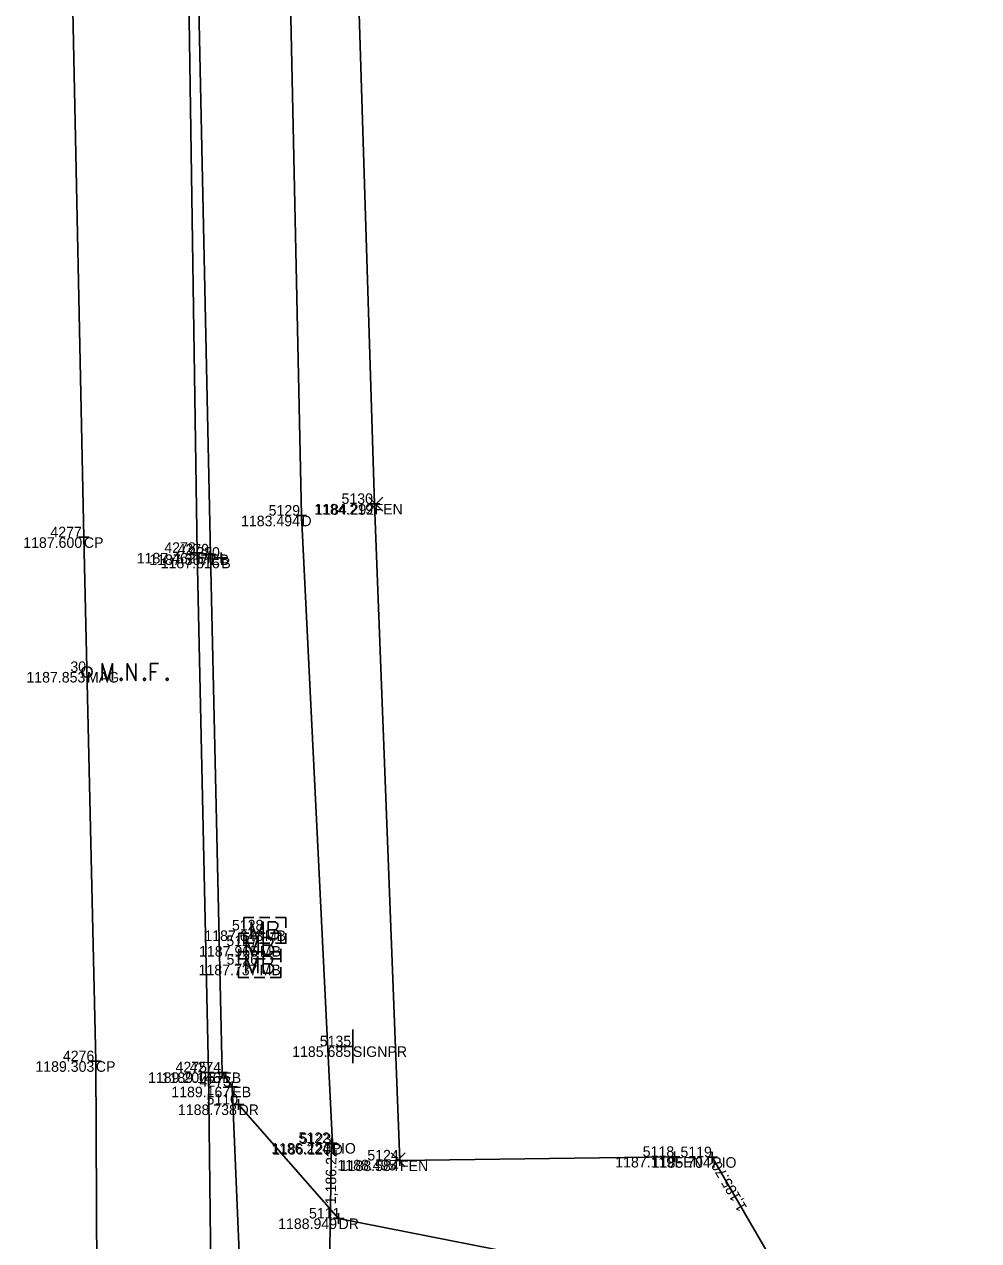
# Model space of a CAD drawing. Extents: x 2044996 to 2050343, y 455232 to 458054.
# Drawn here: x 2047607.5 to 2047697.8, y 457864.6 to 457979.7 of the extents above; entities that cross this region are included whole.
import ezdxf

# ---------------------------------------------------------------- set-up
doc = ezdxf.new("R2010")
doc.units = 0
for name, color, linetype in [('DR_X_Ditch', 7, 'Continuous'), ('DR_X_Elev_Flow', 7, 'Continuous'), ('DR_X_Storm_Sewer', 7, 'Continuous'), ('DT_X_Contour_Major', 7, 'Continuous'), ('DT_X_Contour_Minor', 7, 'Continuous'), ('DT_X_Contour_Text', 7, 'Continuous'), ('DT_X_Spot_Elev', 7, 'Continuous'), ('DT_X_Triangles', 7, 'Continuous'), ('DT_X_Void', 7, 'Continuous'), ('PV_X_COP', 7, 'Continuous'), ('PV_X_Driveway', 7, 'Continuous'), ('PV_X_EOP', 7, 'Continuous'), ('PV_X_Shoulder_Aggregate', 7, 'Continuous'), ('RD_X_Cells', 7, 'Continuous'), ('RD_X_Fence', 7, 'Continuous'), ('SC_Scratch1', 7, 'Continuous'), ('SN_X_Public', 7, 'Continuous')]:
    doc.layers.add(name, color=color, linetype=linetype)

msp = doc.modelspace()

# ---------------------------------------------------------------- linework, layer by layer
at = {"layer": 'DR_X_Ditch'}
msp.add_lwpolyline([(2047636.7, 457873.73), (2047633.74, 457933.19), (2047632.12, 458009.84)], dxfattribs=at)
at = {"layer": 'DR_X_Elev_Flow'}
for p, q in [((2047636.59, 457874.32), (2047636.59, 457873.32)), ((2047636.09, 457873.82), (2047637.09, 457873.82)), ((2047636.59, 457873.82), (2047636.59, 457873.82)), ((2047672.61, 457872.98), (2047672.61, 457871.98)), ((2047672.11, 457872.48), (2047673.11, 457872.48)), ((2047672.61, 457872.48), (2047672.61, 457872.48))]:
    msp.add_line(p, q, dxfattribs=at)
at = {"layer": 'DR_X_Storm_Sewer'}
for p, q in [((2047635.9, 457828.32), (2047636.59, 457873.82)), ((2047697.83, 457829.07), (2047672.61, 457872.48))]:
    msp.add_line(p, q, dxfattribs=at)
at = {"layer": 'DT_X_Contour_Major'}
for points in [[(2047614.89, 457917.59), (2047614.89, 457919.19), (2047615.39, 457917.59), (2047615.88, 457919.19), (2047615.88, 457917.59)], [(2047617.26, 457917.59), (2047617.26, 457919.19), (2047618.08, 457917.59), (2047618.08, 457919.19)], [(2047620.23, 457919.19), (2047619.47, 457919.19), (2047619.47, 457917.59)], [(2047616.65, 457917.8), (2047616.71, 457917.8), (2047616.74, 457917.78), (2047616.77, 457917.73), (2047616.77, 457917.67), (2047616.74, 457917.61), (2047616.71, 457917.59), (2047616.65, 457917.59), (2047616.62, 457917.61), (2047616.58, 457917.67), (2047616.58, 457917.73), (2047616.62, 457917.78), (2047616.65, 457917.8)], [(2047618.87, 457917.8), (2047618.92, 457917.8), (2047618.95, 457917.78), (2047618.99, 457917.73), (2047618.99, 457917.67), (2047618.95, 457917.61), (2047618.92, 457917.59), (2047618.87, 457917.59), (2047618.83, 457917.61), (2047618.8, 457917.67), (2047618.8, 457917.73), (2047618.83, 457917.78), (2047618.87, 457917.8)], [(2047619.47, 457918.41), (2047620.01, 457918.41)], [(2047621.02, 457917.8), (2047621.07, 457917.8), (2047621.1, 457917.78), (2047621.14, 457917.73), (2047621.14, 457917.67), (2047621.1, 457917.61), (2047621.07, 457917.59), (2047621.02, 457917.59), (2047620.98, 457917.61), (2047620.95, 457917.67), (2047620.95, 457917.73), (2047620.98, 457917.78), (2047621.02, 457917.8)]]:
    msp.add_lwpolyline(points, dxfattribs=at)
msp.add_circle((2047613.45, 457918.4), 0.497, dxfattribs=at)
at = {"layer": 'DT_X_Spot_Elev'}
for p, q in [((2047640.11, 457933.6), (2047641.44, 457934.93)), ((2047640.11, 457934.93), (2047641.44, 457933.6)), ((2047642.23, 457871.56), (2047643.56, 457872.89)), ((2047642.23, 457872.89), (2047643.56, 457871.56))]:
    msp.add_line(p, q, dxfattribs=at)
at = {"layer": 'DT_X_Void'}
for p, q in [((2047640.16, 457934.3), (2047641.16, 457934.3)), ((2047640.66, 457934.8), (2047640.66, 457933.8)), ((2047640.66, 457934.3), (2047640.66, 457934.3)), ((2047633.24, 457933.19), (2047634.24, 457933.19)), ((2047633.74, 457933.69), (2047633.74, 457932.69)), ((2047633.74, 457933.19), (2047633.74, 457933.19)), ((2047613.16, 457931.64), (2047613.16, 457930.64)), ((2047612.66, 457931.14), (2047613.66, 457931.14)), ((2047613.16, 457931.14), (2047613.16, 457931.14)), ((2047623.39, 457929.67), (2047624.39, 457929.67)), ((2047623.89, 457930.17), (2047623.89, 457929.17)), ((2047623.89, 457929.67), (2047623.89, 457929.67)), ((2047624.63, 457929.52), (2047625.63, 457929.52)), ((2047625.13, 457930.02), (2047625.13, 457929.02)), ((2047625.13, 457929.52), (2047625.13, 457929.52)), ((2047625.66, 457929.21), (2047626.66, 457929.21)), ((2047626.16, 457929.71), (2047626.16, 457928.71)), ((2047626.16, 457929.21), (2047626.16, 457929.21)), ((2047614.29, 457882.06), (2047614.29, 457881.06)), ((2047613.79, 457881.56), (2047614.79, 457881.56)), ((2047614.29, 457881.56), (2047614.29, 457881.56)), ((2047624.96, 457881.01), (2047624.96, 457880.01)), ((2047626.26, 457881), (2047626.26, 457880)), ((2047624.46, 457880.51), (2047625.46, 457880.51)), ((2047624.96, 457880.51), (2047624.96, 457880.51)), ((2047625.76, 457880.5), (2047626.76, 457880.5)), ((2047626.26, 457880.5), (2047626.26, 457880.5)), ((2047627.2, 457879.65), (2047627.2, 457878.65)), ((2047626.7, 457879.15), (2047627.7, 457879.15)), ((2047627.2, 457879.15), (2047627.2, 457879.15)), ((2047627.29, 457877.47), (2047628.29, 457877.47)), ((2047627.79, 457877.97), (2047627.79, 457876.97)), ((2047627.79, 457877.47), (2047627.79, 457877.47)), ((2047636.7, 457874.23), (2047636.7, 457873.23)), ((2047636.2, 457873.73), (2047637.2, 457873.73)), ((2047636.7, 457873.73), (2047636.7, 457873.73)), ((2047669.05, 457873.01), (2047669.05, 457872.01)), ((2047642.57, 457872.17), (2047643.57, 457872.17)), ((2047643.07, 457872.67), (2047643.07, 457871.67)), ((2047643.07, 457872.17), (2047643.07, 457872.17)), ((2047668.55, 457872.51), (2047669.55, 457872.51)), ((2047669.05, 457872.51), (2047669.05, 457872.51)), ((2047637.26, 457867.18), (2047637.26, 457866.18)), ((2047636.76, 457866.68), (2047637.76, 457866.68)), ((2047637.26, 457866.68), (2047637.26, 457866.68))]:
    msp.add_line(p, q, dxfattribs=at)
at = {"layer": 'PV_X_COP'}
msp.add_lwpolyline([(2047630.7, 457032.77), (2047629.57, 457079.46), (2047628.83, 457121.31), (2047627.83, 457168.37), (2047627.23, 457213.89), (2047626.35, 457261.41), (2047625.27, 457313.88), (2047624.14, 457367.69), (2047623.14, 457414.96), (2047622.16, 457463.48), (2047621.21, 457510.6), (2047620.34, 457561.9), (2047619.47, 457614.83), (2047618.33, 457662.23), (2047617.51, 457713.13), (2047616.39, 457759.38), (2047615.44, 457807.27), (2047614.41, 457854.52), (2047614.29, 457881.56), (2047613.16, 457931.14), (2047612.06, 457984.05), (2047611.48, 458032.26), (2047610.91, 458052.26)], dxfattribs=at)
at = {"layer": 'PV_X_Driveway'}
msp.add_lwpolyline([(2047627.79, 457877.47), (2047637.26, 457866.68), (2047656.32, 457862.93), (2047675.59, 457863.11)], dxfattribs=at)
at = {"layer": 'PV_X_EOP'}
for p, q in [((2047623.89, 457929.67), (2047623.05, 457984.3)), ((2047624.96, 457880.51), (2047623.89, 457929.67)), ((2047625.26, 457852.62), (2047624.96, 457880.51))]:
    msp.add_line(p, q, dxfattribs=at)
at = {"layer": 'PV_X_Shoulder_Aggregate'}
msp.add_lwpolyline([(2047636.93, 457312.89), (2047635.93, 457367.47), (2047634.97, 457414.6), (2047633.92, 457462.12), (2047633.13, 457509.72), (2047632.17, 457560.26), (2047631.16, 457614.81), (2047630.46, 457661.29), (2047629.4, 457713.73), (2047628.5, 457758.09), (2047627.36, 457807.43), (2047627.48, 457822.09), (2047628.61, 457825.87), (2047628.68, 457844.07), (2047627.2, 457879.15), (2047626.26, 457880.5), (2047625.13, 457929.52), (2047623.96, 457984.29), (2047622.9, 458032.45), (2047622.9, 458052.72)], dxfattribs=at)
at = {"layer": 'RD_X_Cells'}
for p, q in [((2047629.77, 457895.16), (2047630.77, 457895.16)), ((2047629.29, 457893.68), (2047630.3, 457893.68)), ((2047630.28, 457893.94), (2047630.28, 457893.94)), ((2047629.77, 457892.72), (2047630.77, 457892.72)), ((2047629.81, 457892.46), (2047629.81, 457892.46)), ((2047629.28, 457891.92), (2047630.28, 457891.92)), ((2047629.29, 457891.24), (2047630.3, 457891.24)), ((2047629.79, 457890.7), (2047629.79, 457890.7)), ((2047629.28, 457889.48), (2047630.28, 457889.48))]:
    msp.add_line(p, q, dxfattribs=at)
for points in [[(2047628.28, 457894.19), (2047628.28, 457895.16), (2047629.25, 457895.16)], [(2047628.99, 457893.14), (2047628.99, 457894.74), (2047629.57, 457893.14), (2047630.12, 457894.74), (2047630.12, 457893.14)], [(2047631.31, 457894.01), (2047631.37, 457894.07), (2047631.41, 457894.11), (2047631.43, 457894.15), (2047631.44, 457894.17), (2047631.47, 457894.22), (2047631.48, 457894.26), (2047631.51, 457894.35), (2047631.51, 457894.39), (2047631.51, 457894.44), (2047631.5, 457894.51), (2047631.47, 457894.58), (2047631.43, 457894.63), (2047631.37, 457894.68), (2047631.32, 457894.7), (2047631.29, 457894.72), (2047631.23, 457894.74), (2047630.61, 457894.74), (2047630.61, 457893.14), (2047631.31, 457893.14), (2047631.39, 457893.19), (2047631.47, 457893.25), (2047631.53, 457893.35), (2047631.57, 457893.47), (2047631.58, 457893.58), (2047631.58, 457893.66), (2047631.56, 457893.73), (2047631.51, 457893.85), (2047631.44, 457893.92), (2047631.31, 457894.01), (2047630.61, 457894.01)], [(2047631.29, 457895.16), (2047632.28, 457895.16), (2047632.28, 457894.19)], [(2047627.81, 457892.71), (2047627.81, 457893.68), (2047628.78, 457893.68)], [(2047629.25, 457892.72), (2047628.28, 457892.72), (2047628.28, 457893.69)], [(2047630.81, 457893.68), (2047631.81, 457893.68), (2047631.81, 457892.71)], [(2047632.28, 457893.69), (2047632.28, 457892.72), (2047631.29, 457892.72)], [(2047628.51, 457891.66), (2047628.51, 457893.26), (2047629.09, 457891.66), (2047629.64, 457893.26), (2047629.64, 457891.66)], [(2047630.83, 457892.53), (2047630.89, 457892.59), (2047630.93, 457892.63), (2047630.95, 457892.67), (2047630.97, 457892.69), (2047630.99, 457892.74), (2047631, 457892.78), (2047631.03, 457892.87), (2047631.03, 457892.91), (2047631.03, 457892.96), (2047631.02, 457893.03), (2047630.99, 457893.1), (2047630.95, 457893.15), (2047630.89, 457893.2), (2047630.84, 457893.22), (2047630.82, 457893.24), (2047630.75, 457893.26), (2047630.14, 457893.26), (2047630.14, 457891.66), (2047630.83, 457891.66), (2047630.92, 457891.71), (2047630.99, 457891.77), (2047631.05, 457891.87), (2047631.09, 457891.99), (2047631.11, 457892.1), (2047631.11, 457892.18), (2047631.08, 457892.25), (2047631.03, 457892.37), (2047630.97, 457892.44), (2047630.83, 457892.53), (2047630.14, 457892.53)], [(2047627.79, 457890.95), (2047627.79, 457891.92), (2047628.76, 457891.92)], [(2047628.78, 457891.24), (2047627.81, 457891.24), (2047627.81, 457892.21)], [(2047628.49, 457889.9), (2047628.49, 457891.5), (2047629.07, 457889.9), (2047629.62, 457891.5), (2047629.62, 457889.9)], [(2047630.81, 457890.77), (2047630.87, 457890.83), (2047630.91, 457890.87), (2047630.94, 457890.91), (2047630.95, 457890.93), (2047630.97, 457890.98), (2047630.99, 457891.02), (2047631.01, 457891.11), (2047631.01, 457891.15), (2047631.01, 457891.2), (2047631, 457891.27), (2047630.97, 457891.34), (2047630.94, 457891.39), (2047630.87, 457891.44), (2047630.82, 457891.46), (2047630.8, 457891.47), (2047630.73, 457891.5), (2047630.12, 457891.5), (2047630.12, 457889.9), (2047630.81, 457889.9), (2047630.9, 457889.95), (2047630.97, 457890.01), (2047631.04, 457890.11), (2047631.07, 457890.23), (2047631.09, 457890.34), (2047631.09, 457890.42), (2047631.06, 457890.49), (2047631.01, 457890.6), (2047630.95, 457890.68), (2047630.81, 457890.77), (2047630.12, 457890.77)], [(2047630.79, 457891.92), (2047631.79, 457891.92), (2047631.79, 457890.95)], [(2047631.81, 457892.21), (2047631.81, 457891.24), (2047630.81, 457891.24)], [(2047628.76, 457889.48), (2047627.79, 457889.48), (2047627.79, 457890.45)], [(2047631.79, 457890.45), (2047631.79, 457889.48), (2047630.79, 457889.48)]]:
    msp.add_lwpolyline(points, dxfattribs=at)
at = {"layer": 'RD_X_Fence'}
msp.add_lwpolyline([(2047669.05, 457872.51), (2047643.07, 457872.17), (2047640.66, 457934.3), (2047638.33, 458008.93)], dxfattribs=at)
at = {"layer": 'SN_X_Public'}
for p, q in [((2047638.61, 457884.57), (2047638.61, 457881.37)), ((2047638.61, 457882.97), (2047637.01, 457882.97))]:
    msp.add_line(p, q, dxfattribs=at)

# ---------------------------------------------------------------- texts
at = {"layer": 'DT_X_Contour_Minor'}
for s, p in [('1184.219', (2047634.95, 457933.3)), ('1184.292', (2047635.05, 457933.27)), ('1183.494', (2047628.03, 457932.19)), ('1187.600', (2047607.42, 457930.14)), ('1187.462', (2047618.16, 457928.67)), ('1187.367', (2047619.35, 457928.52)), ('1187.316', (2047620.43, 457928.21)), ('1187.853', (2047607.72, 457917.4)), ('1187.643', (2047624.56, 457892.94)), ('1187.965', (2047624.06, 457891.46)), ('1187.737', (2047624.01, 457889.7)), ('1185.685', (2047632.87, 457881.97)), ('1189.303', (2047608.57, 457880.56)), ('1189.200', (2047619.23, 457879.51)), ('1189.146', (2047620.52, 457879.5)), ('1189.167', (2047621.43, 457878.15)), ('1188.738', (2047622.06, 457876.47)), ('1186.224', (2047630.88, 457872.82)), ('1186.120', (2047630.97, 457872.73)), ('1188.495', (2047637.15, 457871.23)), ('1188.584', (2047637.37, 457871.17)), ('1187.119', (2047663.44, 457871.51)), ('1185.704', (2047666.9, 457871.48)), ('1188.949', (2047631.54, 457865.68))]:
    msp.add_text(s, height=1, dxfattribs=at).set_placement(p)
at = {"layer": 'DT_X_Contour_Text'}
for s, p in [('FEN', (2047640.66, 457933.3)), ('D', (2047633.74, 457932.19)), ('CP', (2047613.16, 457930.14)), ('EP', (2047623.89, 457928.67)), ('EB', (2047625.13, 457928.52)), ('B', (2047626.16, 457928.21)), ('MAG', (2047613.45, 457917.4)), ('MB', (2047630.28, 457892.94)), ('MB', (2047629.81, 457891.46)), ('MB', (2047629.79, 457889.7)), ('SIGNPR', (2047638.61, 457881.97)), ('CP', (2047614.29, 457880.56)), ('EP', (2047624.96, 457879.51)), ('EB', (2047626.26, 457879.5)), ('EB', (2047627.2, 457878.15)), ('DR', (2047627.79, 457876.47)), ('PIO', (2047636.59, 457872.82)), ('D', (2047636.7, 457872.73)), ('FEN', (2047643.07, 457871.17)), ('FEN', (2047669.05, 457871.51)), ('PIO', (2047672.61, 457871.48)), ('DR', (2047637.26, 457865.68))]:
    msp.add_text(s, height=1, dxfattribs=at).set_placement(p)
at = {"layer": 'DT_X_Triangles'}
for s, p in [('5130', (2047637.54, 457934.3)), ('5129', (2047630.64, 457933.19)), ('4277', (2047609.99, 457931.14)), ('4278', (2047620.77, 457929.67)), ('4279', (2047622.03, 457929.52)), ('4280', (2047623.05, 457929.21)), ('30', (2047611.88, 457918.4)), ('5128', (2047627.17, 457893.94)), ('5127', (2047626.64, 457892.46)), ('5126', (2047626.66, 457890.7)), ('5135', (2047635.48, 457882.97)), ('4276', (2047611.17, 457881.56)), ('4275', (2047621.83, 457880.51)), ('4274', (2047623.17, 457880.5)), ('4273', (2047624.1, 457879.15)), ('5110', (2047624.77, 457877.47)), ('5122', (2047633.47, 457873.82)), ('5123', (2047633.59, 457873.73)), ('5124', (2047639.98, 457872.17)), ('5118', (2047666.04, 457872.51)), ('5119', (2047669.61, 457872.48)), ('5111', (2047634.46, 457866.68))]:
    msp.add_text(s, height=1, dxfattribs=at).set_placement(p)
at = {"layer": 'SC_Scratch1'}
for s, rotation, p in [("1,186.22'", 89.1413, (2047637, 457868.02)), ("1,185.70'", 120.1644, (2047675.95, 457867.71))]:
    msp.add_text(s, height=1, rotation=rotation, dxfattribs=at).set_placement(p)

doc.saveas('drawing.dxf')
